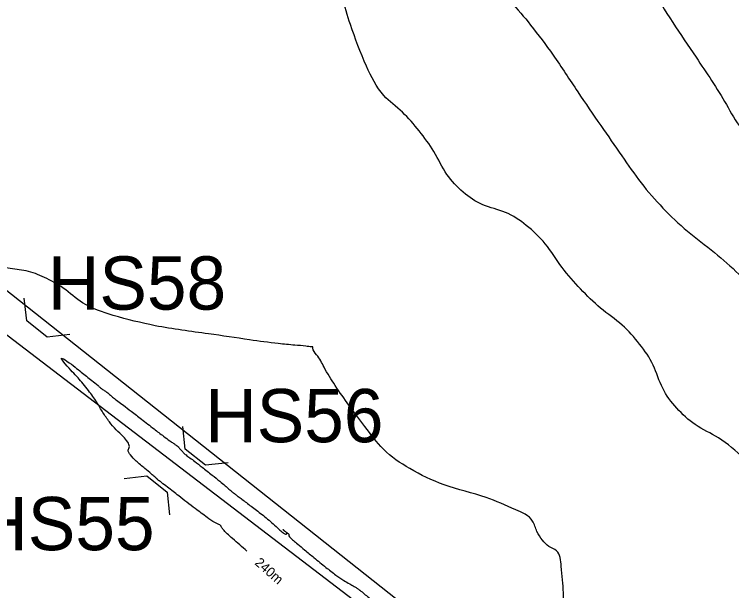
# Model space of a CAD drawing. Extents: x -478495 to -472450, y -1118050 to -1113745.
# Drawn here: x -476976.4 to -476841.8, y -1115126.7 to -1115018.5 of the extents above; entities that cross this region are included whole.
import ezdxf

# ---------------------------------------------------------------- set-up
doc = ezdxf.new("R2010")
doc.units = 0
for name, color, linetype in [('cyklostezka', 7, 'Continuous'), ('hospodářské sjezdy', 7, 'Continuous'), ('silnice', 7, 'Continuous'), ('Vrstevnice_hlavni', 7, 'Continuous'), ('Vrstevnice_popis', 7, 'Continuous'), ('Vrstevnice_vedlejsi', 7, 'Continuous')]:
    doc.layers.add(name, color=color, linetype=linetype)

msp = doc.modelspace()

# ---------------------------------------------------------------- linework, layer by layer
at = {"layer": 'cyklostezka'}
msp.add_lwpolyline([(-477033.5754190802, -1115019.3150603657), (-476978.4562666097, -1115069.8432601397), (-476859.56050309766, -1115163.970078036), (-476838.56618741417, -1115180.4272610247), (-476823.49769734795, -1115192.2844335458), (-476742.0352354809, -1115258.9995421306), (-476654.0177406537, -1115335.224940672), (-476615.8651919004, -1115370.6739552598), (-476567.0504242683, -1115426.523456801)], dxfattribs=at)
at = {"layer": 'hospodářské sjezdy'}
for p, q in [((-476974.108, -1115076.008), (-476974.578838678, -1115071.7686136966)), ((-476970.29539166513, -1115079.0622121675), (-476974.108, -1115076.008)), ((-476966.05543236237, -1115078.5965616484), (-476970.29539166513, -1115079.0622121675)), ((-476944.3871692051, -1115100.087842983), (-476944.85800788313, -1115095.8484566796)), ((-476940.57456087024, -1115103.1420551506), (-476944.3871692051, -1115100.087842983)), ((-476936.33460156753, -1115102.6764046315), (-476940.57456087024, -1115103.1420551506)), ((-476955.8369593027, -1115105.6126505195), (-476951.597, -1115105.1470000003)), ((-476951.597, -1115105.1470000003), (-476947.78439166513, -1115108.2012121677)), ((-476947.78439166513, -1115108.2012121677), (-476947.3135529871, -1115112.440598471))]:
    msp.add_line(p, q, dxfattribs=at)
at = {"layer": 'silnice'}
msp.add_lwpolyline([(-476200.5430969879, -1116268.1533225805), (-476239.9646638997, -1116179.1988064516), (-476260.9335824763, -1116109.5457419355), (-476288.6125549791, -1116007.1641290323), (-476289.4513117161, -1115970.2396129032), (-476274.35369035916, -1115930.797516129), (-476257.5785554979, -1115904.782516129), (-476369.13277385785, -1115816.6670000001), (-476386.7466654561, -1115803.239903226), (-476421.13569191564, -1115718.4813548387), (-476492.4300150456, -1115557.3561935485), (-476531.85169606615, -1115480.150387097), (-476576.30580343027, -1115421.4068387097), (-476632.5025051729, -1115358.4673225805), (-476738.18585476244, -1115266.156032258), (-476821.72644138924, -1115198.097580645), (-476986.4582147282, -1115072.218548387), (-477038.7966192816, -1115021.8669354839), (-477039.4315830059, -1115021.0219319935)], dxfattribs=at)
at = {"layer": 'Vrstevnice_hlavni'}
for points in [[(-476873.251, -1115143.677), (-476873.507, -1115142.01), (-476873.554, -1115139.102), (-476873.522, -1115134.12), (-476873.41000000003, -1115127.063), (-476873.808, -1115122.0860000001), (-476874.717, -1115119.19), (-476876.136, -1115118.374), (-476877.354, -1115117.171), (-476878.371, -1115115.579), (-476879.185, -1115113.6), (-476882.364, -1115111.475), (-476887.908, -1115109.205), (-476895.815, -1115106.789), (-476902.242, -1115103.761), (-476907.186, -1115100.12), (-476910.64900000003, -1115095.867), (-476913.66000000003, -1115091.883), (-476916.218, -1115088.1670000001), (-476918.324, -1115084.72), (-476919.72500000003, -1115082.379), (-476920.42100000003, -1115081.145), (-476920.412, -1115081.017), (-476920.42600000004, -1115080.932), (-476920.462, -1115080.891), (-476920.521, -1115080.893), (-476920.576, -1115080.895), (-476920.62700000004, -1115080.896), (-476920.674, -1115080.898), (-476921.73600000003, -1115080.799), (-476923.814, -1115080.599), (-476926.907, -1115080.3), (-476932.302, -1115079.591), (-476940, -1115078.472), (-476950, -1115076.9440000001), (-476957.876, -1115075.006), (-476963.629, -1115072.6570000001), (-476967.259, -1115069.897), (-476970.802, -1115067.892), (-476974.259, -1115066.643), (-476977.631, -1115066.149), (-476980.601, -1115065.341), (-476983.17, -1115064.218), (-476985.338, -1115062.781), (-476986.878, -1115061.747), (-476987.79000000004, -1115061.118), (-476988.074, -1115060.892), (-476988.478, -1115060.587), (-476989.003, -1115060.204), (-476989.648, -1115059.743), (-476990.332, -1115059.246), (-476991.055, -1115058.714), (-476991.817, -1115058.146), (-476992.891, -1115057.395), (-476994.277, -1115056.46), (-476995.976, -1115055.343), (-476997.039, -1115054.593), (-476997.46400000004, -1115054.21), (-476997.254, -1115054.195), (-476998.009, -1115053.437), (-476999.729, -1115051.937), (-477002.416, -1115049.693), (-477004.444, -1115048.001), (-477005.814, -1115046.86), (-477006.527, -1115046.27), (-477007.324, -1115045.723), (-477008.206, -1115045.2210000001), (-477009.173, -1115044.763), (-477009.833, -1115044.445), (-477010.186, -1115044.267), (-477010.232, -1115044.2280000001), (-477010.318, -1115044.158), (-477010.443, -1115044.058), (-477010.608, -1115043.927), (-477010.86600000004, -1115043.703), (-477011.219, -1115043.389), (-477011.666, -1115042.982), (-477011.859, -1115042.654), (-477011.79600000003, -1115042.405), (-477011.479, -1115042.235), (-477011.695, -1115041.8460000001), (-477012.445, -1115041.236), (-477013.729, -1115040.4070000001), (-477014.642, -1115039.799), (-477015.184, -1115039.41), (-477015.355, -1115039.241), (-477015.476, -1115039.117), (-477015.545, -1115039.038), (-477015.564, -1115039.003), (-477015.672, -1115038.875), (-477015.869, -1115038.653), (-477016.157, -1115038.339), (-477016.405, -1115038.07), (-477016.615, -1115037.849), (-477016.786, -1115037.674), (-477017.213, -1115037.2820000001), (-477017.89400000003, -1115036.673)], [(-476932.792, -1115119.262), (-476935.498, -1115116.888), (-476936.479, -1115116), (-476937.087, -1115115.411), (-476937.32300000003, -1115115.12), (-476937.5, -1115114.875), (-476937.618, -1115114.675), (-476937.677, -1115114.52), (-476937.902, -1115114.338), (-476938.294, -1115114.131), (-476938.853, -1115113.897), (-476940.257, -1115112.9440000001), (-476942.505, -1115111.269), (-476945.599, -1115108.875), (-476947.707, -1115107.241), (-476948.83, -1115106.367), (-476948.968, -1115106.254), (-476949.085, -1115106.163), (-476949.183, -1115106.094), (-476949.259, -1115106.046), (-476949.32300000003, -1115106.009), (-476949.37200000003, -1115105.985), (-476949.408, -1115105.973), (-476949.45, -1115105.9440000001), (-476949.499, -1115105.898), (-476949.555, -1115105.835), (-476949.591, -1115105.789), (-476949.608, -1115105.759), (-476949.604, -1115105.746), (-476949.613, -1115105.727), (-476949.632, -1115105.703), (-476949.663, -1115105.672), (-476949.74700000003, -1115105.601), (-476949.884, -1115105.489), (-476950.074, -1115105.337), (-476950.759, -1115104.761), (-476951.93700000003, -1115103.761), (-476953.608, -1115102.337), (-476954.65400000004, -1115101.176), (-476955.074, -1115100.278), (-476954.868, -1115099.641), (-476955.177, -1115098.795), (-476956.001, -1115097.7380000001), (-476957.33900000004, -1115096.4710000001), (-476958.612, -1115094.975), (-476959.82, -1115093.251), (-476960.962, -1115091.298), (-476962.522, -1115089.122), (-476964.501, -1115086.7210000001), (-476966.89900000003, -1115084.097), (-476967.59500000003, -1115083.05), (-476966.591, -1115083.578), (-476963.886, -1115085.683), (-476961.93200000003, -1115087.218), (-476960.727, -1115088.185), (-476960.273, -1115088.582), (-476959.89, -1115088.8900000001), (-476959.57800000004, -1115089.107), (-476959.337, -1115089.235), (-476959.065, -1115089.426), (-476958.762, -1115089.68), (-476958.427, -1115089.997), (-476957.854, -1115090.467), (-476957.042, -1115091.091), (-476955.99100000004, -1115091.868), (-476954.506, -1115092.9980000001), (-476952.585, -1115094.482), (-476950.23, -1115096.32), (-476948.452, -1115097.6840000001), (-476947.25200000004, -1115098.575), (-476946.631, -1115098.991), (-476946.191, -1115099.29), (-476945.93200000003, -1115099.472), (-476945.855, -1115099.535), (-476945.803, -1115099.579), (-476945.77400000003, -1115099.602), (-476945.77, -1115099.605), (-476945.75800000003, -1115099.615), (-476945.738, -1115099.6300000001), (-476945.712, -1115099.651), (-476945.614, -1115099.762), (-476945.445, -1115099.9610000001), (-476945.205, -1115100.25), (-476944.97000000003, -1115100.5150000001), (-476944.74, -1115100.756), (-476944.515, -1115100.974), (-476944.231, -1115101.209), (-476943.887, -1115101.464), (-476943.485, -1115101.736), (-476942.59, -1115102.412), (-476941.204, -1115103.491), (-476939.325, -1115104.974), (-476937.88, -1115106.138), (-476936.869, -1115106.982), (-476936.293, -1115107.506), (-476935.78, -1115107.952), (-476935.331, -1115108.3190000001)], [(-476935.331, -1115108.3190000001), (-476934.947, -1115108.607), (-476934.41500000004, -1115109.009), (-476933.73600000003, -1115109.525), (-476932.909, -1115110.156), (-476932.006, -1115110.842), (-476931.026, -1115111.583), (-476929.968, -1115112.379), (-476928.913, -1115113.236), (-476927.86, -1115114.154), (-476926.808, -1115115.132), (-476926.037, -1115115.767), (-476925.54600000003, -1115116.058), (-476925.335, -1115116.006), (-476925.325, -1115115.864), (-476925.515, -1115115.632), (-476925.905, -1115115.311), (-476926.044, -1115115.192), (-476925.931, -1115115.276), (-476925.565, -1115115.563), (-476925.29000000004, -1115115.779), (-476925.105, -1115115.925), (-476925.01, -1115116.002), (-476924.95, -1115116.053), (-476924.925, -1115116.079), (-476924.935, -1115116.079), (-476924.936, -1115116.133), (-476924.927, -1115116.239), (-476924.909, -1115116.398), (-476924.628, -1115116.734), (-476924.083, -1115117.247), (-476923.275, -1115117.937), (-476921.987, -1115119.01), (-476920.22000000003, -1115120.464), (-476917.972, -1115122.302), (-476916.102, -1115123.736), (-476914.608, -1115124.768), (-476913.49, -1115125.397), (-476912.67600000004, -1115125.868), (-476912.164, -1115126.18), (-476911.956, -1115126.335), (-476911.795, -1115126.454), (-476911.684, -1115126.538), (-476911.62, -1115126.587), (-476910.788, -1115127.262), (-476909.18700000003, -1115128.562), (-476906.818, -1115130.4880000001), (-476904.666, -1115132.215), (-476902.733, -1115133.742), (-476901.01900000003, -1115135.07), (-476899.74, -1115136.063), (-476898.897, -1115136.7210000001), (-476898.49, -1115137.044), (-476897.79000000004, -1115137.566), (-476896.79600000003, -1115138.286), (-476895.509, -1115139.205), (-476894.623, -1115139.837), (-476894.139, -1115140.183), (-476894.056, -1115140.242), (-476893.9, -1115140.355), (-476893.67, -1115140.521), (-476893.367, -1115140.74), (-476893.126, -1115140.887), (-476892.94800000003, -1115140.962), (-476892.83400000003, -1115140.965), (-476892.748, -1115140.977), (-476892.691, -1115140.997), (-476892.664, -1115141.027), (-476892.601, -1115141.034), (-476892.501, -1115141.018), (-476892.364, -1115140.98), (-476892.219, -1115140.91), (-476892.065, -1115140.81), (-476891.902, -1115140.679), (-476891.793, -1115140.591), (-476891.738, -1115140.546), (-476891.737, -1115140.543), (-476891.726, -1115140.55), (-476891.70300000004, -1115140.565), (-476891.67100000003, -1115140.589), (-476891.32, -1115140.854), (-476890.651, -1115141.361), (-476889.664, -1115142.109), (-476889.038, -1115142.693), (-476888.773, -1115143.114), (-476888.869, -1115143.371), (-476888.96400000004, -1115143.585), (-476889.059, -1115143.757), (-476889.15400000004, -1115143.887), (-476889.202, -1115143.9980000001), (-476889.202, -1115144.091), (-476889.15400000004, -1115144.166), (-476889.109, -1115144.273), (-476889.066, -1115144.412), (-476889.025, -1115144.583), (-476888.922, -1115144.761), (-476888.756, -1115144.947)]]:
    msp.add_spline(points, degree=3, dxfattribs=at)
at = {"layer": 'Vrstevnice_vedlejsi'}
for points in [[(-476863.927, -1114896.656), (-476864.487, -1114897.252), (-476865.071, -1114897.889), (-476865.677, -1114898.565), (-476866.30700000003, -1114899.2820000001), (-476866.805, -1114899.83), (-476867.172, -1114900.208), (-476867.407, -1114900.418), (-476867.74100000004, -1114900.678), (-476868.173, -1114900.9880000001), (-476868.702, -1114901.349), (-476869.233, -1114901.681), (-476869.766, -1114901.984), (-476870.3, -1114902.257), (-476870.94800000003, -1114902.629), (-476871.70900000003, -1114903.1), (-476872.58400000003, -1114903.669), (-476873.168, -1114904.049), (-476873.461, -1114904.24), (-476873.463, -1114904.241), (-476873.55100000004, -1114904.325), (-476873.724, -1114904.492), (-476873.984, -1114904.741), (-476874.161, -1114904.912), (-476874.256, -1114905.006), (-476874.26900000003, -1114905.022), (-476874.36100000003, -1114905.114), (-476874.533, -1114905.2820000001), (-476874.783, -1114905.525), (-476874.968, -1114905.697), (-476875.087, -1114905.797), (-476875.141, -1114905.825), (-476875.305, -1114905.924), (-476875.58, -1114906.092), (-476875.966, -1114906.33), (-476876.15, -1114906.627), (-476876.13, -1114906.982), (-476875.909, -1114907.395), (-476875.411, -1114907.861), (-476874.63800000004, -1114908.381), (-476873.59, -1114908.955), (-476872.4, -1114909.59), (-476871.068, -1114910.288), (-476869.596, -1114911.047), (-476867.984, -1114911.943), (-476866.233, -1114912.974), (-476864.343, -1114914.143), (-476862.26300000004, -1114915.3730000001), (-476859.995, -1114916.6670000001), (-476857.538, -1114918.024), (-476856.288, -1114919.431), (-476856.245, -1114920.888), (-476857.41000000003, -1114922.396), (-476858.29600000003, -1114923.78), (-476858.903, -1114925.038), (-476859.232, -1114926.172), (-476860.136, -1114927.534), (-476861.614, -1114929.1230000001), (-476863.668, -1114930.939), (-476866.109, -1114933.271), (-476868.93700000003, -1114936.117), (-476872.153, -1114939.48), (-476874.972, -1114942.361), (-476877.39400000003, -1114944.76), (-476879.42100000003, -1114946.679), (-476881.284, -1114948.437), (-476882.985, -1114950.034), (-476884.52400000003, -1114951.47), (-476885.685, -1114952.568), (-476886.468, -1114953.327), (-476886.874, -1114953.749), (-476887.08900000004, -1114954.314), (-476887.115, -1114955.022), (-476886.952, -1114955.874), (-476886.822, -1114957.962), (-476886.726, -1114961.286), (-476886.664, -1114965.8460000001), (-476887.319, -1114972.175), (-476888.691, -1114980.271), (-476890.77900000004, -1114990.136), (-476891.863, -1114997.833), (-476891.942, -1115003.364), (-476891.017, -1115006.7280000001), (-476889.27900000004, -1115009.983), (-476886.728, -1115013.128), (-476883.364, -1115016.165), (-476879.572, -1115020.5), (-476875.351, -1115026.134), (-476870.702, -1115033.067), (-476866.397, -1115039.379), (-476862.438, -1115045.0690000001), (-476858.82300000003, -1115050.139), (-476854.722, -1115054.849), (-476850.136, -1115059.2010000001), (-476845.065, -1115063.195), (-476840.461, -1115067.283), (-476836.324, -1115071.465)], [(-476865.118, -1114947.811), (-476865.909, -1114953.905), (-476866.397, -1114959.485), (-476866.583, -1114964.551), (-476866.466, -1114969.101), (-476866.298, -1114975.062), (-476866.079, -1114982.4340000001), (-476865.81, -1114991.217), (-476862.793, -1115001.5), (-476857.028, -1115013.281), (-476848.514, -1115026.563), (-476842.83, -1115035.427), (-476839.976, -1115039.872), (-476839.952, -1115039.9), (-476839.93200000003, -1115039.927), (-476839.916, -1115039.952), (-476839.90400000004, -1115039.976), (-476839.84500000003, -1115040.056), (-476839.73600000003, -1115040.192), (-476839.58, -1115040.384), (-476835.718, -1115044.893), (-476828.15, -1115053.719), (-476816.875, -1115066.861), (-476808.737, -1115076.31), (-476803.734, -1115082.065), (-476801.867, -1115084.127), (-476797.75200000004, -1115089.088), (-476791.389, -1115096.949), (-476782.77900000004, -1115107.71), (-476776.767, -1115115.206), (-476773.353, -1115119.437), (-476772.537, -1115120.403), (-476772.031, -1115121.162), (-476771.83400000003, -1115121.714), (-476771.946, -1115122.0590000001), (-476771.93700000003, -1115122.445), (-476771.806, -1115122.872), (-476771.554, -1115123.34), (-476770.597, -1115124.4980000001), (-476768.934, -1115126.3460000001), (-476766.566, -1115128.885), (-476764.193, -1115131.746), (-476761.815, -1115134.93), (-476759.431, -1115138.437), (-476757.58900000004, -1115140.867), (-476756.286, -1115142.2210000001), (-476755.52400000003, -1115142.497), (-476754.929, -1115142.712), (-476754.5, -1115142.865), (-476754.239, -1115142.958), (-476753.581, -1115143.571), (-476752.527, -1115144.705), (-476751.076, -1115146.36), (-476749.018, -1115148.796), (-476746.353, -1115152.01), (-476743.082, -1115156.0050000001), (-476739.879, -1115159.848), (-476736.745, -1115163.538), (-476733.68, -1115167.0760000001), (-476730.457, -1115172.213), (-476727.076, -1115178.95), (-476723.538, -1115187.285), (-476720.898, -1115193.299), (-476719.156, -1115196.992), (-476718.31200000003, -1115198.364), (-476716.879, -1115200.043), (-476714.858, -1115202.028), (-476712.249, -1115204.321), (-476710.783, -1115206.301), (-476710.45900000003, -1115207.9710000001), (-476711.277, -1115209.329), (-476711.851, -1115210.263), (-476712.181, -1115210.774), (-476712.265, -1115210.862), (-476712.362, -1115210.9980000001), (-476712.472, -1115211.183), (-476712.594, -1115211.4170000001), (-476712.099, -1115212.259), (-476710.98600000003, -1115213.71), (-476709.256, -1115215.769), (-476706.933, -1115218.347), (-476704.018, -1115221.445), (-476700.511, -1115225.062), (-476697.57283116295, -1115227.8820723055)], [(-476757.389, -1115194.577), (-476758.695, -1115193.071), (-476762.715, -1115189.575), (-476769.45, -1115184.09), (-476778.9, -1115176.617), (-476785.233, -1115171.626), (-476788.449, -1115169.12), (-476788.548, -1115169.097), (-476788.61600000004, -1115169.0690000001), (-476788.652, -1115169.036), (-476788.658, -1115168.9980000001), (-476788.97500000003, -1115168.981), (-476789.604, -1115168.985), (-476790.544, -1115169.009), (-476791.34, -1115169.0690000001), (-476791.993, -1115169.163), (-476792.50200000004, -1115169.2920000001), (-476792.841, -1115169.3530000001), (-476793.01, -1115169.345), (-476793.00800000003, -1115169.27), (-476793.01, -1115169.218), (-476793.016, -1115169.19), (-476793.02400000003, -1115169.185), (-476793.11600000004, -1115169.12), (-476793.292, -1115168.995), (-476793.55, -1115168.808), (-476794.162, -1115168.339), (-476795.126, -1115167.587), (-476796.444, -1115166.554), (-476797.585, -1115165.656), (-476798.549, -1115164.894), (-476799.337, -1115164.267), (-476799.874, -1115163.8360000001), (-476800.159, -1115163.599), (-476800.193, -1115163.557), (-476800.227, -1115163.476), (-476800.26, -1115163.355), (-476800.292, -1115163.1940000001), (-476800.74, -1115161.892), (-476801.603, -1115159.447), (-476802.88300000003, -1115155.861), (-476803.7, -1115153.354), (-476804.054, -1115151.925), (-476803.945, -1115151.575), (-476804.007, -1115151.177), (-476804.24, -1115150.731), (-476804.64400000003, -1115150.237), (-476804.919, -1115149.909), (-476805.064, -1115149.746), (-476805.079, -1115149.749), (-476805.08900000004, -1115149.743), (-476805.092, -1115149.729), (-476805.09, -1115149.708), (-476805.189, -1115149.233), (-476805.389, -1115148.305), (-476805.689, -1115146.924), (-476806.577, -1115144.876), (-476808.05100000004, -1115142.162), (-476810.112, -1115138.7820000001), (-476812.7, -1115134.82), (-476815.815, -1115130.275), (-476819.457, -1115125.148), (-476823.762, -1115119.561), (-476828.729, -1115113.513), (-476834.358, -1115107.004), (-476839.556, -1115101.834), (-476844.32300000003, -1115098.003), (-476848.659, -1115095.511), (-476852.145, -1115092.404), (-476854.77900000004, -1115088.6840000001), (-476856.564, -1115084.349), (-476859.10000000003, -1115080.398), (-476862.389, -1115076.832), (-476866.429, -1115073.651), (-476870.181, -1115070.045), (-476873.646, -1115066.014), (-476876.82300000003, -1115061.5590000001), (-476880.36600000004, -1115058.1130000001), (-476884.273, -1115055.676), (-476888.547, -1115054.2480000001), (-476892.21, -1115051.872), (-476895.264, -1115048.547), (-476897.708, -1115044.273), (-476900.496, -1115040.378), (-476903.629, -1115036.861), (-476907.106, -1115033.723), (-476910.359, -1115028.232), (-476913.387, -1115020.389), (-476916.191, -1115010.195), (-476918.00800000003, -1115003.154), (-476918.83900000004, -1114999.267), (-476918.684, -1114998.534), (-476918.744, -1114997.862), (-476919.01900000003, -1114997.249), (-476919.51, -1114996.697), (-476920.516, -1114995.4340000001), (-476922.039, -1114993.459)]]:
    msp.add_spline(points, degree=3, dxfattribs=at)

# ---------------------------------------------------------------- texts
at = {"layer": 'hospodářské sjezdy'}
for s, p in [('HS58', (-476970.14762869, -1115073.9241577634)), ('HS56', (-476940.6292115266, -1115098.8165543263)), ('HS55', (-476983.58511710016, -1115119.0829302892))]:
    msp.add_text(s, height=9.999999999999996, rotation=359.99999385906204, dxfattribs=at).set_placement(p)
at = {"layer": 'Vrstevnice_popis'}
msp.add_text(' 240m ', height=1.8, rotation=318.5874926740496, dxfattribs=at).set_placement((-476931.97000000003, -1115121.188))

doc.saveas('drawing.dxf')
